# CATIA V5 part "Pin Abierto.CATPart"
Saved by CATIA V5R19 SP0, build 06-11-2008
Part number: Pin Abierto
Publications: "Plane.1"
Material "Chroma": density 7190 kg/m3, Young's modulus 7e+10 Pa, Poisson ratio 0.3, thermal expansion 6.2e-06 1/K
Bounding box of the stored display mesh (mm): x -115.8 to 115.8, y -13.2 to 13.2, z -13.2 to 13.2
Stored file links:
  E:\Luis\Dropbox\3DIT\Parking\planos\cat 3 dit park8\Cadena\Pin Abierto.CATPart
  E:\Luis\Dropbox\3DIT\Parking\planos\cat 3 dit park8\Cadena\Eslabon de Cadena.........................................CATProduct
  E:\Luis\Dropbox\3DIT\Parking\planos\cat 3 dit park8\Cadena\Parametros cadena.CATPart
  C:\Program Files (x86)\Dassault Systemes\B19\intel_a\startup\materials\Catalog.CATMaterial
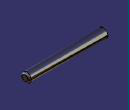
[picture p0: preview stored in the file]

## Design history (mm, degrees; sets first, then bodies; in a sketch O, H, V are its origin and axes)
Parameters
  d2 = 26.4
  i2 = 154.4
AxisSystem1: origin (0, 0, 0), X (1, 0, 0), Y (0, 1, 0), Z (0, 0, 1)
Set1
  Plane1: stored without definition
Body1 (main body), material "Chroma"
  Sketch1 on yz-plane, origin (0, 0, 0), H (0, 1, 0), V (0, 0, 1)
    circle A1 centre (0, 0) radius 13.2
    radius A1 = 13.2 {= d2 /2/1000}
  Pad1: profile Sketch1, direction (-1, 0, 0), length 115.8 {= i2*3/4/1000}, mirrored extent
  Fillet1: radius 5, on edge [end face of Pad1 | face of Pad1 from Sketch1.A1]; edge [face of Pad1 from Sketch1.A1 | start face of Pad1]
Relations
  Pad1.SecondLimit.Length = `External Parameters\i2` /2/1000 (deactivated)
